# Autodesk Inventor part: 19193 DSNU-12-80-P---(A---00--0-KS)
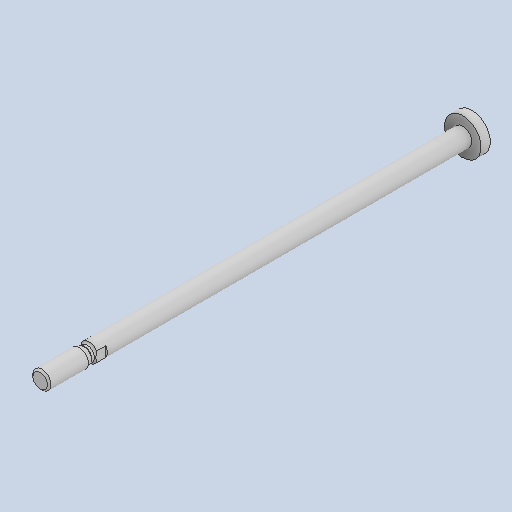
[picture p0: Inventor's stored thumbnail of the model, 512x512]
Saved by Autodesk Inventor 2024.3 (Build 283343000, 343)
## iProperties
Created: 2024-12
Part Number: 19193 DSNU-12-80-P---(A---00--0-KS)
Material: Generic
Description: 19193 DSNU-12-80-P---(A---00--0-KS)
Document SubType Name: Modeling
Designer: ruhr
Density: 1 g/cm^3
Appearance: Default
Author: ruhr
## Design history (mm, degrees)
feature "19193 DSNU-12-80-P---(A---00--0-KS)"
body "Solid1"
